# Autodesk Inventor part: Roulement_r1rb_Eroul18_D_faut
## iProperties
Created: 2011-10
Part Number: Roulement_r1rb_Eroul18_D_faut
Document SubType Name: Modeling
Designer: Bruno
Author: Bruno
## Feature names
1. Base1
